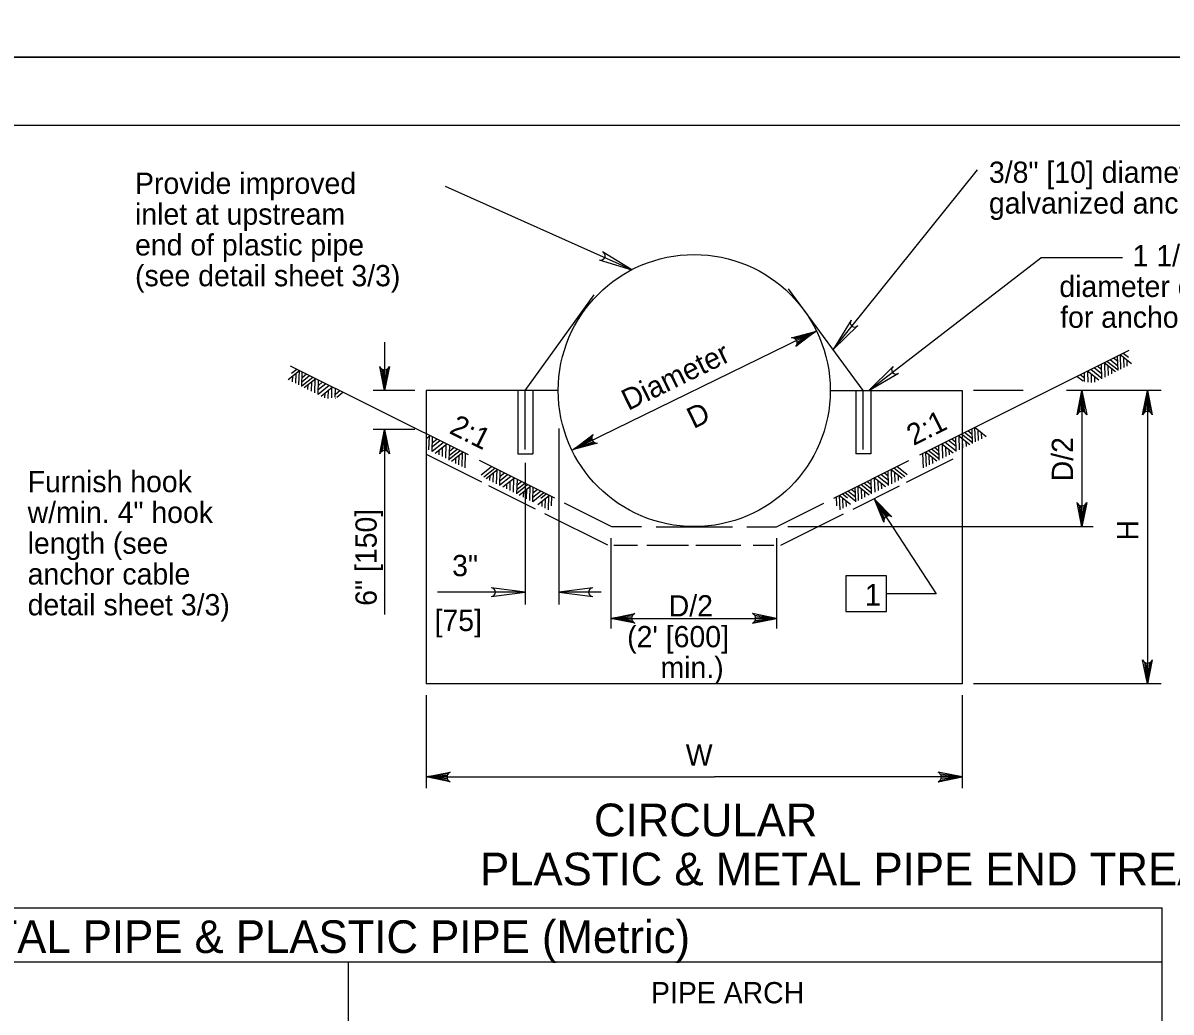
# Model space of a CAD drawing. Extents: x 1083.1 to 1117.1, y 675.4 to 741.4.
# Drawn here: x 1095.29 to 1103.72, y 712.34 to 719.6 of the extents above; entities that cross this region are included whole.
import ezdxf

# ---------------------------------------------------------------- set-up
doc = ezdxf.new("R2010")
doc.units = 0
doc.layers.add('Level 1', color=7, linetype='Continuous')
doc.layers.add('Level 44', color=7, linetype='Continuous')

msp = doc.modelspace()

# ---------------------------------------------------------------- linework, layer by layer
at = {"layer": 'Level 1'}
for p, q in [((1101.2427, 717.2078), (1102.3034, 718.5256)), ((1099.7653, 717.793), (1098.3973, 718.4042)), ((1101.5055, 716.9057), (1102.7669, 717.8795)), ((1103.3676, 717.8795), (1102.7669, 717.8795)), ((1101.4642, 716.9057), (1100.9161, 717.6536)), ((1098.9821, 716.9057), (1099.4875, 717.6079)), ((1101.1205, 717.3433), (1099.3258, 716.4682)), ((1100.9562, 717.2908), (1101.1128, 717.3395)), ((1100.9663, 717.2841), (1101.1128, 717.3395)), ((1100.9752, 717.2724), (1101.1128, 717.3395)), ((1100.9787, 717.2615), (1101.1128, 717.3395)), ((1100.9787, 717.2492), (1101.1128, 717.3395)), ((1097.9496, 717.2604), (1097.9496, 716.9057)), ((1101.8806, 716.4329), (1103.4171, 717.2012)), ((1103.3348, 717.0553), (1103.2539, 717.1196)), ((1103.3339, 717.0861), (1103.2774, 717.1313)), ((1103.333, 717.1182), (1103.3016, 717.1433)), ((1103.3348, 717.0519), (1103.3315, 717.1587)), ((1103.4342, 717.1016), (1103.3509, 717.168)), ((1103.3563, 717.0627), (1103.353, 717.1658)), ((1103.4111, 717.1477), (1103.3724, 717.1787)), ((1103.3799, 717.0745), (1103.3773, 717.1467)), ((1103.4027, 717.0859), (1103.4013, 717.1278)), ((1097.2427, 716.9863), (1097.326, 717.0527)), ((1098.5658, 716.4329), (1097.2598, 717.0859)), ((1097.2658, 717.0325), (1097.3045, 717.0635)), ((1097.3207, 716.9474), (1097.3239, 717.0505)), ((1097.3421, 716.9367), (1097.3454, 717.0434)), ((1097.9272, 717.0659), (1097.9496, 716.9057)), ((1097.9382, 717.0605), (1097.9496, 716.9057)), ((1097.9743, 717.0678), (1097.9496, 716.9057)), ((1097.964, 717.0617), (1097.9496, 716.9057)), ((1097.9496, 717.0588), (1097.9496, 716.9057)), ((1103.0894, 716.9721), (1103.0875, 717.0363)), ((1103.1933, 716.9812), (1103.1098, 717.0475)), ((1103.1158, 716.9679), (1103.1137, 717.0443)), ((1103.2158, 716.9954), (1103.1347, 717.06)), ((1103.2147, 717.0284), (1103.1598, 717.0725)), ((1103.2133, 717.0593), (1103.1827, 717.084)), ((1103.2158, 716.9924), (1103.2126, 717.0989)), ((1103.3166, 717.0427), (1103.2327, 717.109)), ((1103.2397, 717.0043), (1103.2368, 717.1057)), ((1103.2645, 717.0167), (1103.2622, 717.0857)), ((1103.2897, 717.0292), (1103.2883, 717.0649)), ((1097.2742, 716.9707), (1097.2756, 717.0125)), ((1097.297, 716.9592), (1097.2996, 717.0314)), ((1097.3421, 716.94), (1097.423, 717.0042)), ((1097.343, 716.9708), (1097.3995, 717.016)), ((1097.3439, 717.0028), (1097.3753, 717.0281)), ((1097.3603, 716.9275), (1097.4442, 716.9937)), ((1097.3872, 716.914), (1097.3886, 716.9497)), ((1097.4124, 716.9014), (1097.4147, 716.9705)), ((1097.4372, 716.8891), (1097.4402, 716.9904)), ((1097.4611, 716.8771), (1097.4643, 716.9837)), ((1097.4623, 716.9132), (1097.5172, 716.9572)), ((1097.4637, 716.944), (1097.4942, 716.9688)), ((1103.0784, 716.9738), (1103.0335, 717.0093)), ((1103.0887, 716.9957), (1103.0572, 717.0212)), ((1103.0897, 716.9649), (1103.0881, 716.9662)), ((1103.141, 716.964), (1103.1392, 717.0242)), ((1103.1656, 716.9674), (1103.1645, 717.004)), ((1097.4612, 716.8801), (1097.5422, 716.9447)), ((1097.4837, 716.8658), (1097.5672, 716.9322)), ((1097.5113, 716.8521), (1097.5124, 716.8887)), ((1097.5359, 716.8487), (1097.5377, 716.909)), ((1097.5611, 716.8527), (1097.5632, 716.9291)), ((1097.5875, 716.8567), (1097.5894, 716.9211)), ((1097.5883, 716.8803), (1097.6198, 716.9059)), ((1097.5985, 716.8585), (1097.6434, 716.8941)), ((1098.1718, 716.9057), (1097.8663, 716.9057)), ((1098.2551, 716.9057), (1098.2551, 714.7529)), ((1099.2247, 716.9057), (1098.2551, 716.9057)), ((1098.9272, 716.9057), (1098.9272, 716.4424)), ((1098.9821, 716.4723), (1098.9821, 716.9057)), ((1099.037, 716.9057), (1099.037, 716.4424)), ((1101.2217, 716.9057), (1102.1912, 716.9057)), ((1101.2217, 716.9057), (1102.1912, 716.9057)), ((1101.4093, 716.9057), (1101.4093, 716.4424)), ((1101.4642, 716.4723), (1101.4642, 716.9057)), ((1101.5192, 716.9057), (1101.5192, 716.4424)), ((1102.1912, 716.9057), (1102.1912, 714.7529)), ((1102.6387, 716.9057), (1102.2746, 716.9057)), ((1103.6512, 716.9057), (1102.9562, 716.9057)), ((1103.0448, 716.7436), (1103.0695, 716.9057)), ((1103.0551, 716.7497), (1103.0695, 716.9057)), ((1103.0695, 716.9057), (1103.0695, 716.2198)), ((1103.0695, 716.7525), (1103.0695, 716.9057)), ((1103.0808, 716.7508), (1103.0695, 716.9057)), ((1103.0919, 716.7454), (1103.0695, 716.9057)), ((1103.5261, 716.7436), (1103.5508, 716.9057)), ((1103.5364, 716.7497), (1103.5508, 716.9057)), ((1103.5508, 716.9057), (1103.5508, 715.7052)), ((1103.5508, 716.7525), (1103.5508, 716.9057)), ((1103.5622, 716.7508), (1103.5508, 716.9057)), ((1103.5732, 716.7454), (1103.5508, 716.9057)), ((1097.5873, 716.8496), (1097.5888, 716.8508)), ((1098.1718, 716.6192), (1097.8663, 716.6192)), ((1097.9248, 716.4571), (1097.9496, 716.6192)), ((1097.9352, 716.4633), (1097.9496, 716.6192)), ((1097.9496, 716.6192), (1097.9496, 715.2613)), ((1097.9496, 716.4661), (1097.9496, 716.6192)), ((1097.9609, 716.4644), (1097.9496, 716.6192)), ((1097.972, 716.459), (1097.9496, 716.6192)), ((1099.2283, 716.6268), (1099.2283, 715.3345)), ((1102.2662, 716.5177), (1102.2629, 716.6244)), ((1102.3656, 716.5673), (1102.2823, 716.6338)), ((1102.2877, 716.5284), (1102.2844, 716.6316)), ((1102.3113, 716.5403), (1102.3087, 716.6124)), ((1098.2551, 716.5534), (1098.2822, 716.5747)), ((1098.2752, 716.4702), (1098.2782, 716.5714)), ((1098.2991, 716.4582), (1098.3023, 716.5646)), ((1098.3003, 716.4942), (1098.3553, 716.5382)), ((1098.3017, 716.5251), (1098.3322, 716.5498)), ((1099.4713, 716.564), (1099.337, 716.4737)), ((1099.4713, 716.5517), (1099.337, 716.4737)), ((1099.4747, 716.5408), (1099.337, 716.4737)), ((1099.4836, 716.5291), (1099.337, 716.4737)), ((1102.146, 716.4942), (1102.0912, 716.5382)), ((1102.1447, 716.5251), (1102.1142, 716.5498)), ((1102.1472, 716.4582), (1102.144, 716.5646)), ((1102.248, 716.5086), (1102.1642, 716.5747)), ((1102.1712, 716.4702), (1102.1682, 716.5714)), ((1102.2662, 716.521), (1102.1853, 716.5853)), ((1102.1958, 716.4825), (1102.1936, 716.5515)), ((1102.2653, 716.5518), (1102.2088, 716.597)), ((1102.2212, 716.4951), (1102.2197, 716.5308)), ((1102.2644, 716.5838), (1102.2329, 716.6091)), ((1102.3342, 716.5517), (1102.3327, 716.5935)), ((1098.2993, 716.4612), (1098.3802, 716.5258)), ((1098.3217, 716.4469), (1098.4052, 716.5132)), ((1098.3493, 716.4331), (1098.3506, 716.4697)), ((1098.3738, 716.4208), (1098.3758, 716.49)), ((1098.3984, 716.4086), (1098.4012, 716.5102)), ((1098.4243, 716.3957), (1098.4275, 716.5022)), ((1098.4253, 716.4307), (1098.4815, 716.4752)), ((1098.4262, 716.4614), (1098.4578, 716.487)), ((1098.4409, 716.3873), (1098.5242, 716.4538)), ((1098.464, 716.4335), (1098.5027, 716.4645)), ((1098.5188, 716.3483), (1098.5221, 716.4515)), ((1098.5403, 716.3376), (1098.5437, 716.4443)), ((1099.4937, 716.5224), (1099.337, 716.4737)), ((1101.9061, 716.3376), (1101.9027, 716.4443)), ((1102.0054, 716.3873), (1101.9223, 716.4538)), ((1101.9275, 716.3483), (1101.9243, 716.4515)), ((1101.9823, 716.4335), (1101.9437, 716.4645)), ((1102.021, 716.4307), (1101.9648, 716.4752)), ((1102.0201, 716.4614), (1101.9885, 716.487)), ((1102.0221, 716.3957), (1102.0188, 716.5022)), ((1102.1247, 716.4469), (1102.0412, 716.5132)), ((1102.0479, 716.4086), (1102.0451, 716.5102)), ((1102.1471, 716.4612), (1102.0662, 716.5258)), ((1102.0726, 716.4208), (1102.0706, 716.49)), ((1102.0971, 716.4331), (1102.0958, 716.4697)), ((1098.6643, 716.2329), (1098.2621, 716.4338)), ((1098.4245, 716.4022), (1098.464, 716.4335)), ((1098.4723, 716.3716), (1098.4738, 716.4135)), ((1098.4952, 716.3602), (1098.4977, 716.4323)), ((1099.1987, 716.1167), (1098.6466, 716.3926)), ((1098.9272, 716.4424), (1099.037, 716.4424)), ((1098.9821, 716.3763), (1098.9821, 715.3345)), ((1101.2477, 716.1167), (1101.7997, 716.3926)), ((1101.5192, 716.4424), (1101.4093, 716.4424)), ((1101.7821, 716.2329), (1102.1242, 716.4039)), ((1101.9512, 716.3602), (1101.9486, 716.4323)), ((1101.974, 716.3716), (1101.9725, 716.4135)), ((1102.0218, 716.4022), (1101.9823, 716.4335)), ((1098.6588, 716.2877), (1098.7347, 716.3486)), ((1098.6772, 716.2725), (1098.7581, 716.3368)), ((1098.6955, 716.2601), (1098.7793, 716.3262)), ((1098.7223, 716.2466), (1098.7237, 716.2822)), ((1098.7475, 716.234), (1098.7498, 716.3029)), ((1098.7722, 716.2217), (1098.7752, 716.3229)), ((1098.7962, 716.2097), (1098.7994, 716.3161)), ((1098.7962, 716.2127), (1098.8773, 716.2772)), ((1098.7973, 716.2457), (1098.8523, 716.2898)), ((1098.7987, 716.2765), (1098.8293, 716.3012)), ((1101.6501, 716.2127), (1101.5691, 716.2772)), ((1101.649, 716.2457), (1101.594, 716.2898)), ((1101.6476, 716.2765), (1101.6171, 716.3012)), ((1101.6502, 716.2097), (1101.6469, 716.3161)), ((1101.7509, 716.2601), (1101.6671, 716.3262)), ((1101.6741, 716.2217), (1101.6712, 716.3229)), ((1101.7691, 716.2725), (1101.6882, 716.3368)), ((1101.6988, 716.234), (1101.6965, 716.3029)), ((1101.7876, 716.2877), (1101.7117, 716.3486)), ((1101.7241, 716.2466), (1101.7227, 716.2822)), ((1099.0574, 716.0363), (1098.7149, 716.2076)), ((1098.8187, 716.1984), (1098.9023, 716.2647)), ((1098.8464, 716.1846), (1098.8476, 716.2212)), ((1098.8708, 716.1723), (1098.8729, 716.2415)), ((1098.8956, 716.16), (1098.8984, 716.2617)), ((1098.9213, 716.1471), (1098.9245, 716.2537)), ((1098.9223, 716.1822), (1098.9785, 716.2267)), ((1098.9233, 716.2129), (1098.9548, 716.2385)), ((1098.9379, 716.1387), (1099.0213, 716.2053)), ((1098.961, 716.185), (1098.9997, 716.2161)), ((1099.0159, 716.0998), (1099.0191, 716.203)), ((1099.0373, 716.0892), (1099.0407, 716.1959)), ((1101.389, 716.0363), (1101.7315, 716.2076)), ((1101.409, 716.0892), (1101.4057, 716.1959)), ((1101.5084, 716.1387), (1101.4251, 716.2053)), ((1101.4304, 716.0998), (1101.4272, 716.203)), ((1101.4853, 716.185), (1101.4466, 716.2161)), ((1101.524, 716.1822), (1101.4678, 716.2267)), ((1101.523, 716.2129), (1101.4915, 716.2385)), ((1101.525, 716.1471), (1101.5218, 716.2537)), ((1101.6276, 716.1984), (1101.5441, 716.2647)), ((1101.5508, 716.16), (1101.548, 716.2617)), ((1101.5755, 716.1723), (1101.5735, 716.2415)), ((1101.5999, 716.1846), (1101.5987, 716.2212)), ((1103.0695, 716.2198), (1103.0695, 715.9062)), ((1098.9217, 716.1537), (1098.961, 716.185)), ((1098.9694, 716.1232), (1098.9709, 716.165)), ((1098.9923, 716.1117), (1098.9948, 716.1838)), ((1099.0373, 716.0925), (1099.1182, 716.1568)), ((1099.0383, 716.1232), (1099.0948, 716.1684)), ((1099.0393, 716.1553), (1099.0707, 716.1806)), ((1099.0749, 716.0703), (1099.1582, 716.1368)), ((1099.0979, 716.1166), (1099.1367, 716.1475)), ((1099.1291, 716.0432), (1099.1317, 716.1155)), ((1099.1527, 716.0314), (1099.156, 716.1345)), ((1099.1755, 716.0604), (1099.1776, 716.1275)), ((1101.2708, 716.0604), (1101.2687, 716.1275)), ((1101.3715, 716.0703), (1101.2882, 716.1368)), ((1101.2936, 716.0314), (1101.2903, 716.1345)), ((1101.3484, 716.1166), (1101.3097, 716.1475)), ((1101.3173, 716.0432), (1101.3147, 716.1155)), ((1101.409, 716.0925), (1101.3282, 716.1568)), ((1101.408, 716.1232), (1101.3516, 716.1684)), ((1101.4071, 716.1553), (1101.3757, 716.1806)), ((1101.4541, 716.1117), (1101.4516, 716.1838)), ((1101.4769, 716.1232), (1101.4754, 716.165)), ((1101.5248, 716.1537), (1101.4853, 716.185)), ((1101.6313, 715.9802), (1101.5465, 716.1076)), ((1101.6209, 715.9697), (1101.5465, 716.1076)), ((1101.6157, 715.9589), (1101.5465, 716.1076)), ((1101.6418, 715.985), (1101.5465, 716.1076)), ((1101.6539, 715.9867), (1101.5465, 716.1076)), ((1099.1063, 716.0547), (1099.1077, 716.0966)), ((1099.6192, 715.9062), (1099.2716, 716.0801)), ((1100.8273, 715.9062), (1101.1747, 716.0801)), ((1101.3401, 716.0547), (1101.3386, 716.0966)), ((1103.0471, 716.0665), (1103.0695, 715.9062)), ((1103.0582, 716.0611), (1103.0695, 715.9062)), ((1103.0942, 716.0684), (1103.0695, 715.9062)), ((1103.0839, 716.0622), (1103.0695, 715.9062)), ((1103.0695, 716.0594), (1103.0695, 715.9062)), ((1099.5885, 715.7707), (1099.1267, 716.0016)), ((1100.8579, 715.7707), (1101.3197, 716.0016)), ((1099.837, 715.9062), (1099.6192, 715.9062)), ((1099.9426, 715.9062), (1100.5038, 715.9062)), ((1100.6093, 715.9062), (1100.8273, 715.9062)), ((1103.1528, 715.9062), (1100.9105, 715.9062)), ((1099.6105, 715.823), (1099.6105, 715.1597)), ((1099.6332, 715.7707), (1099.8071, 715.7707)), ((1099.876, 715.7707), (1100.1822, 715.7707)), ((1100.2342, 715.7707), (1100.566, 715.7707)), ((1100.6547, 715.7707), (1100.8082, 715.7707)), ((1100.8273, 715.823), (1100.8273, 715.1597)), ((1103.5508, 715.7052), (1103.5508, 714.7529)), ((1101.3362, 715.5452), (1101.3362, 715.2835)), ((1101.635, 715.5452), (1101.3362, 715.5452)), ((1101.635, 715.2835), (1101.635, 715.5452)), ((1098.9821, 715.4257), (1098.3392, 715.4257)), ((1099.5398, 715.4257), (1099.2283, 715.4257)), ((1102.0006, 715.4143), (1101.635, 715.4143)), ((1101.3362, 715.2835), (1101.635, 715.2835)), ((1099.7707, 715.2561), (1099.6105, 715.2337)), ((1099.7652, 715.245), (1099.6105, 715.2337)), ((1099.6105, 715.2337), (1100.8273, 715.2337)), ((1099.7637, 715.2337), (1099.6105, 715.2337)), ((1099.7665, 715.2192), (1099.6105, 715.2337)), ((1099.7726, 715.2088), (1099.6105, 715.2337)), ((1100.6651, 715.2088), (1100.8273, 715.2337)), ((1100.667, 715.2561), (1100.8273, 715.2337)), ((1100.6712, 715.2192), (1100.8273, 715.2337)), ((1100.6724, 715.245), (1100.8273, 715.2337)), ((1100.6741, 715.2337), (1100.8273, 715.2337)), ((1103.5284, 714.9132), (1103.5508, 714.7529)), ((1103.5395, 714.9077), (1103.5508, 714.7529)), ((1103.5757, 714.9151), (1103.5508, 714.7529)), ((1103.5652, 714.9089), (1103.5508, 714.7529)), ((1103.5508, 714.9061), (1103.5508, 714.7529)), ((1102.1912, 714.7529), (1098.2551, 714.7529)), ((1103.6512, 714.7529), (1102.2746, 714.7529)), ((1098.2551, 714.6697), (1098.2551, 713.9862)), ((1102.1912, 714.6697), (1102.1912, 713.9862)), ((1098.4153, 714.092), (1098.2551, 714.0696)), ((1102.031, 714.092), (1102.1912, 714.0696)), ((1098.4099, 714.0809), (1098.2551, 714.0696)), ((1098.2551, 714.0696), (1100.3726, 714.0696)), ((1098.4082, 714.0696), (1098.2551, 714.0696)), ((1098.4111, 714.0552), (1098.2551, 714.0696)), ((1098.4172, 714.0448), (1098.2551, 714.0696)), ((1102.1912, 714.0696), (1100.3726, 714.0696)), ((1102.0291, 714.0448), (1102.1912, 714.0696)), ((1102.0352, 714.0552), (1102.1912, 714.0696)), ((1102.0364, 714.0809), (1102.1912, 714.0696)), ((1102.0381, 714.0696), (1102.1912, 714.0696)), ((1086.4782, 713.1088), (1103.6581, 713.1088)), ((1103.6581, 698.2602), (1103.6581, 713.1088)), ((1103.6581, 712.7091), (1086.4782, 712.7091)), ((1097.6841, 699.1592), (1097.6841, 712.7091))]:
    msp.add_line(p, q, dxfattribs=at)
for points in [[(1083.1264, 719.3541), (1117.1264, 719.3541), (1117.1264, 741.3541), (1083.1264, 741.3541)], [(1083.1264, 697.3541), (1117.1264, 697.3541), (1117.1264, 719.3541), (1083.1264, 719.3541)], [(1083.1264, 697.3541), (1117.1264, 697.3541), (1117.1264, 719.3541), (1083.1264, 719.3541)], [(1085.1264, 718.8541), (1116.6264, 718.8541), (1116.6264, 697.8541), (1085.1264, 697.8541)]]:
    msp.add_lwpolyline(points, close=True, dxfattribs=at)
for points in [[(1100.9382, 717.2937), (1101.1128, 717.3395), (1100.9692, 717.2302)], [(1097.985, 717.0827), (1097.9496, 716.9057), (1097.9142, 717.0827)], [(1103.0341, 716.7287), (1103.0695, 716.9057), (1103.1049, 716.7287)], [(1103.5154, 716.7287), (1103.5508, 716.9057), (1103.5863, 716.7287)], [(1097.9142, 716.4422), (1097.9496, 716.6192), (1097.985, 716.4422)], [(1099.5117, 716.5194), (1099.337, 716.4737), (1099.4806, 716.583)], [(1101.6152, 715.9407), (1101.5465, 716.1076), (1101.674, 715.9798)], [(1101.5465, 716.1076), (1102.0006, 715.4143)], [(1103.1049, 716.0833), (1103.0695, 715.9062), (1103.0341, 716.0833)], [(1099.7875, 715.1983), (1099.6105, 715.2337), (1099.7875, 715.2691)], [(1100.6502, 715.1983), (1100.8273, 715.2337), (1100.6502, 715.2691)], [(1103.5863, 714.9299), (1103.5508, 714.7529), (1103.5154, 714.9299)], [(1098.4321, 714.0342), (1098.2551, 714.0696), (1098.4321, 714.105)], [(1102.0142, 714.0342), (1102.1912, 714.0696), (1102.0142, 714.105)]]:
    msp.add_lwpolyline(points, dxfattribs=at)
for centre, start, end in [((1100.9409, 717.2556), 318.08187, 93.90799), ((1097.9495, 717.097), 202.08782, 337.91395), ((1103.0695, 716.7144), 22.08782, 157.91395), ((1103.5509, 716.7144), 22.08782, 157.91395), ((1099.509, 716.5575), 138.08186, 273.90799), ((1097.9496, 716.428), 22.08782, 157.91395), ((1103.0695, 716.0975), 202.08782, 337.91395), ((1101.6526, 715.9484), 55.73666, 191.56279), ((1099.8018, 715.2337), 112.08782, 247.91395), ((1100.6359, 715.2337), 292.08605, 67.91218), ((1103.5508, 714.9442), 202.08782, 337.91395), ((1098.4464, 714.0696), 112.08782, 247.91395), ((1102, 714.0696), 292.08605, 67.91218)]:
    msp.add_arc(centre, 0.0382, start, end, dxfattribs=at)
msp.add_ellipse((1100.2232, 716.9057), major_axis=(0.9986, 0), ratio=0.999895, dxfattribs=at)
at = {"layer": 'Level 44'}
for p, q in [((1099.7653, 717.793), (1099.5498, 717.9235)), ((1099.5243, 717.8664), (1099.7653, 717.793)), ((1101.3752, 717.4222), (1101.2427, 717.2078)), ((1101.2427, 717.2078), (1101.4238, 717.383)), ((1101.6843, 717.0832), (1101.5055, 716.9057)), ((1101.5055, 716.9057), (1101.7225, 717.0337)), ((1098.9821, 715.4257), (1098.7321, 715.457)), ((1099.4783, 715.457), (1099.2283, 715.4257)), ((1098.7321, 715.3945), (1098.9821, 715.4257)), ((1099.2283, 715.4257), (1099.4783, 715.3945))]:
    msp.add_line(p, q, dxfattribs=at)
for centre, radius, start, end in [((1099.5371, 717.895), 0.0313, 245.92685, 65.92685), ((1101.3995, 717.4026), 0.0312, 141.16916, 321.16916), ((1101.7034, 717.0584), 0.0313, 127.6687, 307.6687), ((1098.7321, 715.4257), 0.0312, 270, 90), ((1099.4783, 715.4257), 0.0312, 90, 270)]:
    msp.add_arc(centre, radius, start, end, dxfattribs=at)

# ---------------------------------------------------------------- texts
at = {"layer": 'Level 1'}
for s, height, p in [('3/8" [10] diameter 7X19', 0.156, (1102.387, 718.4304)), ('Provide improved', 0.156, (1096.1173, 718.3494)), ('galvanized anchor cable', 0.156, (1102.387, 718.2044)), ('inlet at upstream', 0.156, (1096.1173, 718.1234)), ('end of plastic pipe', 0.156, (1096.1173, 717.8974)), ('1 1/2" [38]', 0.156, (1103.4423, 717.8187)), ('(see detail sheet 3/3)', 0.156, (1096.1173, 717.6714)), ('diameter opening', 0.156, (1102.9037, 717.5927)), ('for anchor cable', 0.156, (1102.9101, 717.3667)), ('Furnish hook', 0.156, (1095.3287, 716.1599)), ('w/min. 4" hook', 0.156, (1095.3287, 715.9339)), ('length (see', 0.156, (1095.3287, 715.7079)), ('3"', 0.156, (1098.4457, 715.5433)), ('anchor cable', 0.156, (1095.3287, 715.4819)), ('1', 0.16, (1101.475, 715.3259)), ('detail sheet 3/3)', 0.156, (1095.3287, 715.2559)), ('D/2', 0.156, (1100.036, 715.2477)), ('[75]', 0.156, (1098.3164, 715.1405)), ("(2' [600]", 0.156, (1099.7308, 715.0217)), ('min.)', 0.156, (1099.9758, 714.7957)), ('W', 0.156, (1100.161, 714.1529)), ('CIRCULAR', 0.24, (1099.4871, 713.634)), ('PLASTIC & METAL PIPE END TREATMENT "A" W/ ANCHOR CABLE OPTION', 0.24, (1098.6507, 713.2742)), ('CAST IN PLACE HW FOR CORRUGATED METAL PIPE & PLASTIC PIPE (Metric)', 0.24, (1088.3161, 712.7773)), ('PIPE ARCH', 0.156, (1099.9059, 712.4082))]:
    msp.add_text(s, height=height, dxfattribs=at).set_placement(p)
for s, rotation, p in [('Diameter', 25.9977, (1099.7383, 716.7555)), ('D', 25.9977, (1100.2188, 716.6227)), ('2:1', 333.43737, (1098.4166, 716.5965)), ('2:1', 26.56263, (1101.833, 716.4982)), ('D/2', 90.00001, (1103.0044, 716.2398)), ('6" [150]', 90, (1097.8916, 715.3259)), ('H', 90.00001, (1103.484, 715.8054))]:
    msp.add_text(s, height=0.156, rotation=rotation, dxfattribs=at).set_placement(p)

doc.saveas('drawing.dxf')
